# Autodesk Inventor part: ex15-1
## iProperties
Created: 2006-03
Part Number: ex15-1
Document SubType Name: Modeling
Designer: Elise Moss
Author: Elise Moss
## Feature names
1. Extrusion1
2. Hole1
3. Shell1
4. Chamfer1
